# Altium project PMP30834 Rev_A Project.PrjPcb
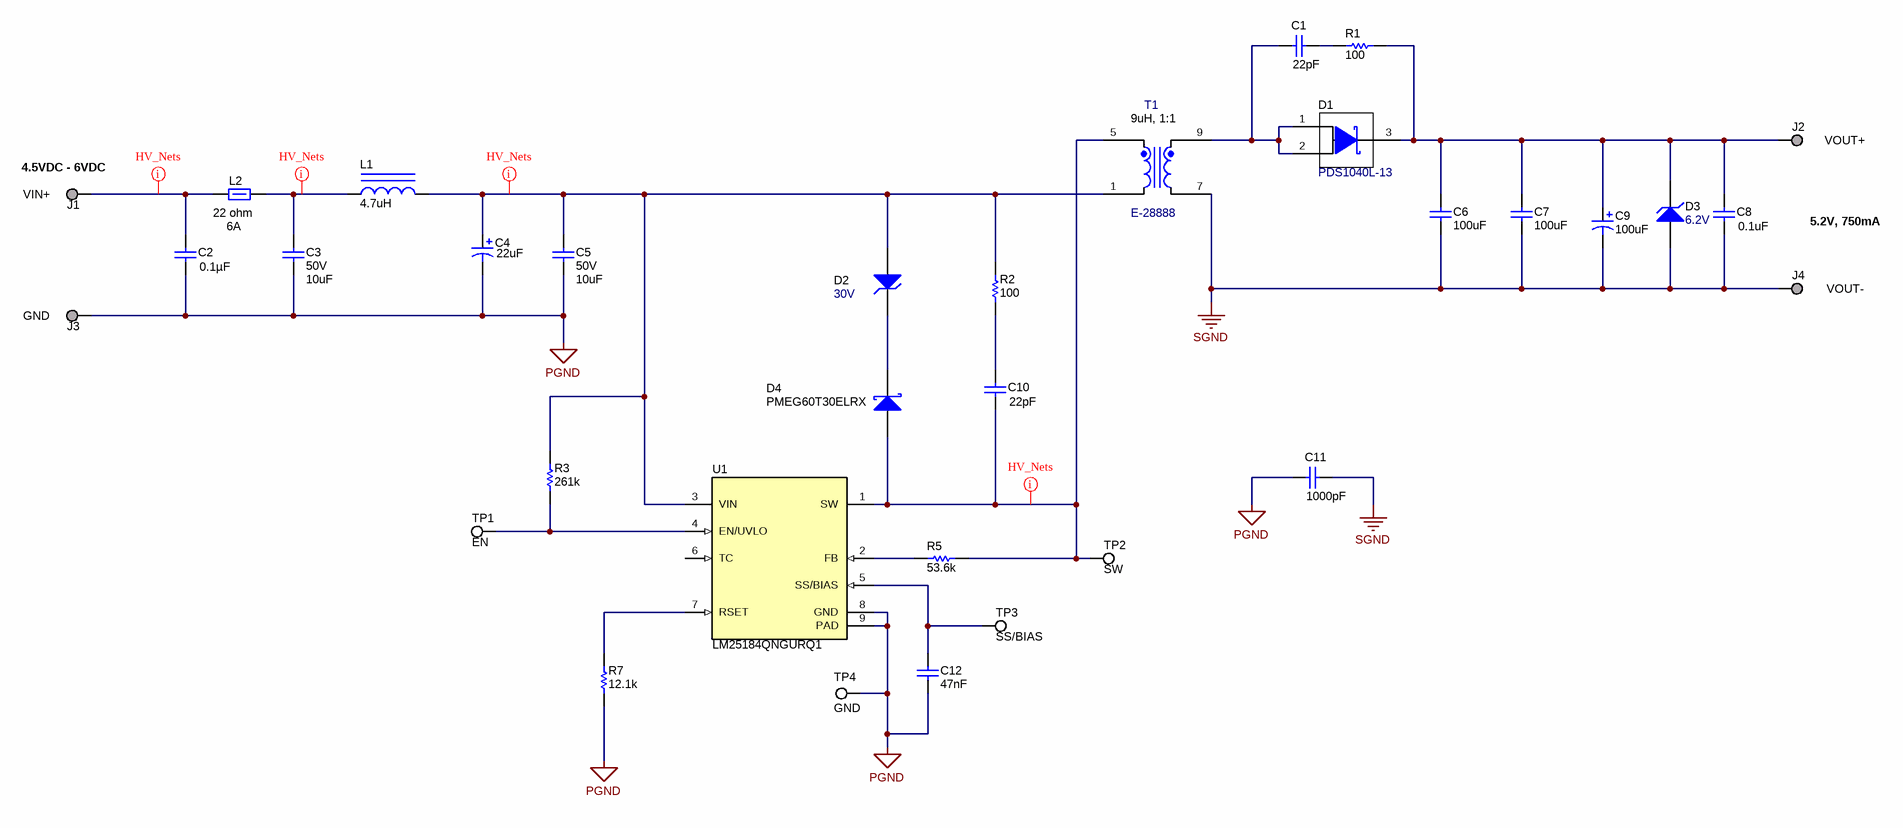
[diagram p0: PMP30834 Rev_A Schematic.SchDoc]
TID: N/A; TechSupport: http://www.ti.com/support; SCH_Rev: A; PRJ_Title: LM25184 Flyback Converter; PRJ_Number: PMP30834; PRJ_Engineer: R. Scibilia; PRJ_Customer: Public Release; PCB_Rev: A; PCB_Layout: K Nielson; CopyrightYear: 2020
2 sheets, 54 parts. Net scope: global (net labels, ports and power ports of the same name join across sheets).
Board file: PMP30834 Rev_A PCB.PcbDoc
Sheets:
  PMP30834 Rev_A Schematic.SchDoc
  PMP30834 Rev_A-HW.SchDoc

## Sheet PMP30834 Rev_A Schematic.SchDoc: LM25184 Flyback Converter - Schematic
size 431 x 279 mm; Date: Not shown in title block; ApprovedBy: Not shown in title block; CheckedBy: Not shown in title block; Author: Not shown in title block; CompanyName: Not shown in title block; DrawnBy: R. Scibilia; Engineer: Not shown in title block; Organization: Not shown in title block; Address1: Not shown in title block; Address2: Not shown in title block; Address3: Not shown in title block; Address4: Not shown in title block; DocumentNumber: 1; Revision: Use project parameter SCH_Rev; SheetNumber: 1; SheetTotal: 2; PageSetup: Record=PageOptions¦CenterHorizontal=True¦CenterVertical=True¦PrintScale=1.00¦XCorrection=1.00¦YCorrection=1.00¦PrintKind=0¦BorderSize=5000000¦LeftOffset=0¦BottomOffset=0¦Orientation=2¦PaperLength=1000¦PaperWidth=1000¦Scale=100¦PaperSource=15¦PrintQuality=600¦MediaType=1¦DitherType=10¦PaperKind=Letter¦PrintScaleMode=1

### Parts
C1  ValueDisplayed: 22pF  [0603_HV]  (hidden comment: GRM1885C2A220JA01D)
C2  ValueDisplayed: 0.1µF  [0603]  (hidden comment: C0603C104K5RACAUTO)
C3  VDC_V: 50V  ValueDisplayed: 10uF  [1210_280]  (hidden comment: CGA6P3X7S1H106K250AB)
C4  ValueDisplayed: 22uF  [Panasonic_D]  (hidden comment: EEH-ZC1H220P)
C5  VDC_V: 50V  ValueDisplayed: 10uF  [1210_280]  (hidden comment: CGA6P3X7S1H106K250AB)
C6  ValueDisplayed: 100uF  [1210_280]  (hidden comment: C1210C107M9PACTU)
C7  ValueDisplayed: 100uF  [1210_280]  (hidden comment: C1210C107M9PACTU)
C8  value 0.1uF  [0603L]  (hidden comment: C0603C104K5RACAUTO)
C9  ValueDisplayed: 100uF  [7343-31]  (hidden comment: T598D107M016ATE050)
C10  ValueDisplayed: 22pF  [0603_HV]  (hidden comment: GRM1885C2A220JA01D)
C11  ValueDisplayed: 1000pF  [1206_190]  (hidden comment: 202R18W102KV4E)
C12  Cap_F: 47nF  [0603L]  (hidden comment: GCM188R71E473KA37D)
D1  PDS1040L-13  [POWERDI5]
D2  value 30V  [SMA]  (hidden comment: 3SMAJ5936B-TP)
D3  value 6.2V  [SOD-523]  (hidden comment: BZT52C6V2T-7)
D4  PMEG60T30ELRX  [SOD-123W]
J1  1573-2  [Keystone1573-2]  (value not drawn)
J2  1573-2  [Keystone1573-2]  (value not drawn)
J3  1573-2  [Keystone1573-2]  (value not drawn)
J4  1573-2  [Keystone1573-2]  (value not drawn)
L1  ValueDisplayed: 4.7uH  [XFL4030]  (hidden comment: XFL4030-472MEB)
L2  value 22 ohm  Value2: 6A  [0805_HV]  (hidden comment: 742792021)
R1  ValueDisplayed: 100  [0603L]  (hidden comment: CRCW0603100RFKEA)
R2  ValueDisplayed: 100  [0603L]  (hidden comment: CRCW0603100RFKEA)
R3  ValueDisplayed: 261k  [0603_HV]  (hidden comment: CRCW0603261KFKEA)
R5  ValueDisplayed: 53.6k  [0603]  (hidden comment: RC0603FR-0753K6L)
R7  ValueDisplayed: 12.1k  [0603L]  (hidden comment: CRCW060312K1FKEA)
T1  E-28888  ValueDisplayed: 9uH, 1:1  [Coilcraft_PA6719-AE]
TP1  EN  [Testpoint_Keystone_Miniature]
TP2  SW  [Testpoint_Keystone_Miniature]
TP3  SS/BIAS  [Testpoint_Keystone_Miniature]
TP4  GND  [Testpoint_Keystone_Miniature]
U1  LM25184QNGURQ1  [NGU0008C]

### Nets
PGND: C2.2 C3.1 C4.2(-) C5.1 C11.2 C12.2 J3.1 R7.1 TP4.1 U1.8(GND) U1.9(PAD)
SGND: C6.1 C7.1 C8.2 C9.2(-) C11.1 D3.2(A) J4.1 T1.7
NetC1_1: C1.1 R1.2
NetC1_2: C1.2 D1.1(A) D1.2(A) T1.9
NetC2_1: C2.1 J1.1 L2.1
NetC3_2: C3.2 L1.1 L2.2
NetC4_1: C4.1(+) C5.2 D2.2(A) L1.2 R2.2 R3.2 T1.1 U1.3(VIN)
NetC6_2: C6.2 C7.2 C8.1 C9.1(+) D1.3(K) D3.1(K) J2.1 R1.1
NetC10_1: C10.1 R2.1
NetC10_2: C10.2 D4.2(A) R5.2 T1.5 TP2.1 U1.1(SW)
NetC12_1: C12.1 TP3.1 U1.5(SS/BIAS)
NetD2_1: D2.1(K) D4.1(K)
NetR3_1: R3.1 TP1.1 U1.4(EN/UVLO)
NetR5_1: R5.1 U1.2(FB)
NetR7_2: R7.2 U1.7(RSET)

Not connected (* = marked no-connect by the designer): U1 6(TC)

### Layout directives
net class HV_Nets: NetC2_1, NetC3_2, NetC4_1, NetC10_2

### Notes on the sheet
- (near J1) 4.5VDC - 6VDC
- (near J2) VOUT+
- (near J1) VIN+
- 5.2V, 750mA
- (near J3) GND
- (near J4) VOUT-

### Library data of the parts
C1 = CMP-0007255-4: CAP, CERM, 22 pF, 100 V, +/- 5%, C0G/NP0, 0603; Manufacturer: MuRata; TaMin_C: -55°C; Polarized: N; SizeAreaWB_mm2: 4.68; U/M: EA; Value: 22pF; TaMax_C: 125°C; SizeZ_mm: 1; SizeX_mm: 1.6; SizeY_mm: 0.8; Cap_Case: 0603; Value2: 100V; SizeArea_mm2: 1.28; CompType: Capacitor; AEC Category: Q200; Value1: Unknown
C2 = CMP-0079602-1: CAP, CERM, 0.1 µF, 50 V,+/- 10%, X7R, AEC-Q200 Grade 1, 0603; Manufacturer: Kemet; TaMin_C: -55°C; Polarized: N; SizeAreaWB_mm2: 4.68; U/M: EA; Value: 0.1uF; TaMax_C: 125°C; SizeZ_mm: 1; SizeX_mm: 1.6; SizeY_mm: 0.8; Value2: 50V; SizeArea_mm2: 1.28; AEC Qualified: Y; Cap_F: 100nF; AEC Category: Q200
C3 C5 = CMP-0009164-2: CAP, CERM, 10 uF, 50 V, +/- 10%, X7S, AEC-Q200 Grade 1, 1210; Manufacturer: TDK; TaMin_C: -55°C; Polarized: N; SizeAreaWB_mm2: 14.7; Value1: 0.002827 ohm; U/M: EA; Value: 10uF; TaMax_C: 125°C; SizeZ_mm: 2.8; SizeX_mm: 3.2; SizeY_mm: 2.5; SizeArea_mm2: 8; AEC Qualified: Y; Cap_F: 10µF; AEC Grade: 1; AEC Category: Q200; ESR_ohm: 2.827m; IRMS_A: 4.37286A
C4 = CMP-0012597-3: CAP, Polymer Hybrid, 22 uF, 50 V, +/- 20%, 0.08 ohm, AEC-Q200 Grade 1, D6.3xL5.8mm SMD; Manufacturer: Panasonic; TaMin_C: -55°C; ESR_ohm: 0.08; Polarized: Y; SizeAreaWB_mm2: 73.96; Value: 22uF; TaMax_C: 125°C; SizeZ_mm: 6.1; SizeX_mm: 6.6; Cap_Case: 6.3x5.8; Value2: 50V; SizeArea_mm2: 43.56; CompType: Capacitor; Cap_F: 22µF; IRMS_A: 750mA; AEC Grade: 1; AEC Category: Q200
C6 C7 = CMP-0009083-2: CAP, CERM, 100 uF, 6.3 V, +/- 20%, X5R, 1210; Manufacturer: Kemet; TaMin_C: -55°C; Polarized: N; SizeAreaWB_mm2: 14.7; Value1: Unknown; U/M: EA; Value: 100uF; TaMax_C: 85°C; SizeZ_mm: 2.8; SizeX_mm: 3.2; SizeY_mm: 2.5; Cap_Case: 1210; Value2: 6.3V; SizeArea_mm2: 8; Cap_F: 100µF; AEC Category: Q200
C8 = CMP-0079602-1: CAP, CERM, 0.1 µF, 50 V,+/- 10%, X7R, AEC-Q200 Grade 1, 0603; Manufacturer: Kemet; TaMin_C: -55°C; Polarized: N; SizeAreaWB_mm2: 4.68; U/M: EA; TaMax_C: 125°C; SizeZ_mm: 1; SizeX_mm: 1.6; SizeY_mm: 0.8; Cap_Case: 0603; Value2: 50V; SizeArea_mm2: 1.28; AEC Qualified: Y; Cap_F: 100nF; AEC Category: Q200; ValueDisplayed: 0.1µF
C9 = CMP-0012660-3: CAP, Tantalum Polymer, 100 uF, 16 V, +/- 20%, 0.05 ohm, AEC-Q200 Grade 1, 7343-31 SMD; Manufacturer: Kemet; TaMin_C: -55°C; ESR_ohm: 0.05; Polarized: Y; SizeAreaWB_mm2: 58.59; Value: 100uF; TaMax_C: 125°C; SizeZ_mm: 3.1; SizeX_mm: 7.3; SizeY_mm: 4.3; Value2: 16V; SizeArea_mm2: 31.39; CompType: Capacitor; Cap_F: 100µF; IRMS_A: 2.121A; AEC Grade: 1; AEC Category: Q200
C10 = CMP-0007255-4: CAP, CERM, 22 pF, 100 V, +/- 5%, C0G/NP0, 0603; Manufacturer: MuRata; TaMin_C: -55°C; Polarized: N; SizeAreaWB_mm2: 4.68; Value1: Unknown; U/M: EA; Value: 22pF; TaMax_C: 125°C; SizeZ_mm: 1; SizeX_mm: 1.6; SizeY_mm: 0.8; Cap_Case: 0603; Value2: 100V; SizeArea_mm2: 1.28; CompType: Capacitor; AEC Category: Q200
C11 = CMP-0008572-2: CAP, CERM, 1000 pF, 2000 V, +/- 10%, X7R, 1206_190; Manufacturer: Johanson Technology; TaMin_C: -55°C; Polarized: N; SizeAreaWB_mm2: 10.92; Value1: Unknown; U/M: EA; Value: 1000pF; TaMax_C: 125°C; SizeZ_mm: 1.9; SizeX_mm: 3.2; SizeY_mm: 1.6; Cap_Case: 1206; Value2: 2000V; SizeArea_mm2: 5.12; CompType: Capacitor; Cap_F: 1nF; VDC_V: 2kV; AEC Category: Q200
C12 = CMP-0007141-3: CAP, CERM, 0.047 uF, 25 V, +/- 10%, X7R, AEC-Q200 Grade 1, 0603; Manufacturer: MuRata; TaMin_C: -55°C; Polarized: N; SizeAreaWB_mm2: 4.68; Value1: Unknown; U/M: EA; TaMax_C: 125°C; SizeZ_mm: 1; SizeX_mm: 1.6; SizeY_mm: 0.8; Cap_Case: 0603; Value2: 25V; SizeArea_mm2: 1.28; AEC Qualified: Y; AEC Category: Q200
D1 = CMP-0028634-2: Diode, Schottky, 40 V, 10 A, PowerDI5; Manufacturer: Diodes Inc.; Value2: 0.49V; Vf_V: 490mV; AEC Category: Q101; Value1: 10A; RJC_CperW: 85; Green_Lifecycle: Active; SizeY_mm: 3.9; SizeArea_mm2: 24.96; Vr_V: 40V; Green_REACh: Passed; SizeX_mm: 6.4; TJmax_C: 150°C; SizeZ_mm: 1.05; SizeAreaWB_mm2: 49.56
D2 = CMP-0005515-3: Diode, Zener, 30 V, 3 W, SMA; Manufacturer: Micro Commercial Components; SizeArea_mm2: 16.3228; Value1: 3W; SizeY_mm: 2.92; SizeX_mm: 5.59; RJA_CperW: 226; SizeZ_mm: 2.87; SizeAreaWB_mm2: 37.3428; AEC Category: Q101
D3 = CMP-0005901-1: Diode, Zener, 6.2 V, 300 mW, SOD-523; Manufacturer: Diodes Inc.; Power_W: 300mW; SizeAreaWB_mm2: 5.13; Value1: 0.3W; RJA_CperW: 417; U/M: EA; SizeZ_mm: 0.65; SizeX_mm: 1.7; SizeY_mm: 0.9; SizeArea_mm2: 1.53; AEC Category: Q101
D4 = CMP-0085903-1: Diode, Schottky, 60 V, 3 A, AEC-Q101, SOD-123W; Manufacturer: Nexperia; Io_A: 3A; SizeAreaWB_mm2: 12.15; Vr_V: 60V; TJmax_C: 175°C; SizeZ_mm: 1; SizeX_mm: 3.5; SizeY_mm: 1.7; Vf_V: 620mV; Value2: 0.62V; SizeArea_mm2: 5.95; AEC Qualified: Y; AEC Category: Q101
J1-J4 = CMP-0055119-1: Terminal, Turret, TH, Double; Manufacturer: Keystone; CT: FALSE; Green_REACh: Passed; CompType: Turret Terminal; Green_Lifecycle: Active
L1 = CMP-0061153-1: Inductor, Shielded, Composite, 4.7 uH, 2.1 A, 0.03 ohm, SMD; Manufacturer: Coilcraft; Isat: 2.1A @ 30% inductance drop; Irms: 7.5A @ 40C rise; Green_Lifecycle: Not Set; SizeAreaWB_mm2: 25; DCR_ohm: 0.03; Green_REACh: Incomplete; Value: 4.7uH; Imax_A: 2.1A; SizeZ_mm: 3.1; SizeX_mm: 4; SizeArea_mm2: 16; Ind_H: 4.7µH; AEC Qualified: N; AEC Category: Q200
L2 = CMP-0003072-1: Ferrite Bead, 22 ohm @ 100 MHz, 6 A, 0805; Manufacturer: Wurth Elektronik; Ztyp@1GHz_Ohm: 40.219; ZTyp@100MHz_Ohm: 22; SizeAreaWB_mm2: 6.75; DCR_ohm: 8m; Value1: 0.008 ohm; SizeZ_mm: 1.45; SizeX_mm: 2; SizeY_mm: 1.25; SizeArea_mm2: 2.5
R1 R2 = CMP-0021991-4: RES, 100, 1%, 0.1 W, AEC-Q200 Grade 0, 0603; Manufacturer: Vishay-Dale; Power_W: 100mW; TempCo: 100 ppm/C; Value_Code: 100R; Value: 100; EIA_Code: E96; SizeX_mm: 1.6; SizeY_mm: 0.8; SizeZ_mm: 1; Value2: 0.1W; SizeArea_mm2: 1.28; AEC Qualified: Y; VDC_V: 75V; AEC Category: Q200; AEC Grade: 0
R3 = CMP-0022244-4: RES, 261 k, 1%, 0.1 W, AEC-Q200 Grade 0, 0603; Manufacturer: Vishay-Dale; Power_W: 100mW; TempCo: 100 ppm/C; Value: 261k; EIA_Code: E96; SizeX_mm: 1.6; SizeY_mm: 0.8; SizeZ_mm: 1; Value2: 0.1W; SizeArea_mm2: 1.28; AEC Qualified: Y; VDC_V: 75V; AEC Category: Q200; AEC Grade: 0
R5 = CMP-0023176-5: RES, 53.6 k, 1%, 0.1 W, 0603; Manufacturer: Yageo; Power_W: 100mW; TempCo: 100 ppm/C; Value_Code: 53k6; Value: 53.6k; EIA_Code: E96; SizeX_mm: 1.6; SizeY_mm: 0.8; SizeZ_mm: 1; Value2: 0.1W; SizeArea_mm2: 1.28; AEC Qualified: N; VDC_V: 75V; AEC Category: Q200; SizeAreaWB_mm2: 4.68
R7 = CMP-0022030-4: RES, 12.1 k, 1%, 0.1 W, AEC-Q200 Grade 0, 0603; Manufacturer: Vishay-Dale; Power_W: 100mW; TempCo: 100 ppm/C; Value_Code: 12k1; Value: 12.1k; EIA_Code: E96; SizeX_mm: 1.6; SizeY_mm: 0.8; SizeZ_mm: 1; Value2: 0.1W; SizeArea_mm2: 1.28; AEC Qualified: Y; VDC_V: 75V; AEC Category: Q200; AEC Grade: 0
T1 = CMP-0030170-2: Transformer, Flyback, SMT; Manufacturer: Custom; LeakageInd_H: 500nH; Ind_H: 9µH; Lp: 9; DCR_ohm: 45m
TP1-TP4 = CMP-0055152-1: Test Point, Miniature, SMT; Manufacturer: Keystone; PartNumber: 5015; CNHeader: FALSE; Green_Lifecycle: Active; Green_REACh: Passed; CT: TRUE
U1 = CMP-0860959-2: 42-VIN PSR Flyback DC/DC Converter with 65-V, 4-A Integrated MOSFET, NGU0008C (WSON-8); Manufacturer: Texas Instruments; SizeArea_mm2: 16; SizeY_mm: 4; SizeAreaWB_mm2: 25; CompType: IC; AEC Category: Q200; SizeZ_mm: 0.8; AEC Qualified: Y

## Sheet PMP30834 Rev_A-HW.SchDoc: LM25184 Flyback Converter - Hardware
size 431 x 279 mm; Date: Not shown in title block; ApprovedBy: Not shown in title block; CheckedBy: Not shown in title block; Author: Not shown in title block; CompanyName: Not shown in title block; DrawnBy: R. Scibilia; Engineer: Not shown in title block; Organization: Not shown in title block; Address1: Not shown in title block; Address2: Not shown in title block; Address3: Not shown in title block; Address4: Not shown in title block; DocumentNumber: 2; Revision: Use project parameter SCH_Rev; SheetNumber: 2; SheetTotal: 2; PageSetup: Record=PageOptions¦CenterHorizontal=True¦CenterVertical=True¦PrintScale=1.00¦XCorrection=1.00¦YCorrection=1.00¦PrintKind=0¦BorderSize=5000000¦LeftOffset=0¦BottomOffset=0¦Orientation=2¦PaperLength=1000¦PaperWidth=1000¦Scale=100¦PaperSource=15¦PrintQuality=600¦MediaType=1¦DitherType=10¦PaperKind=Letter¦PrintScaleMode=1
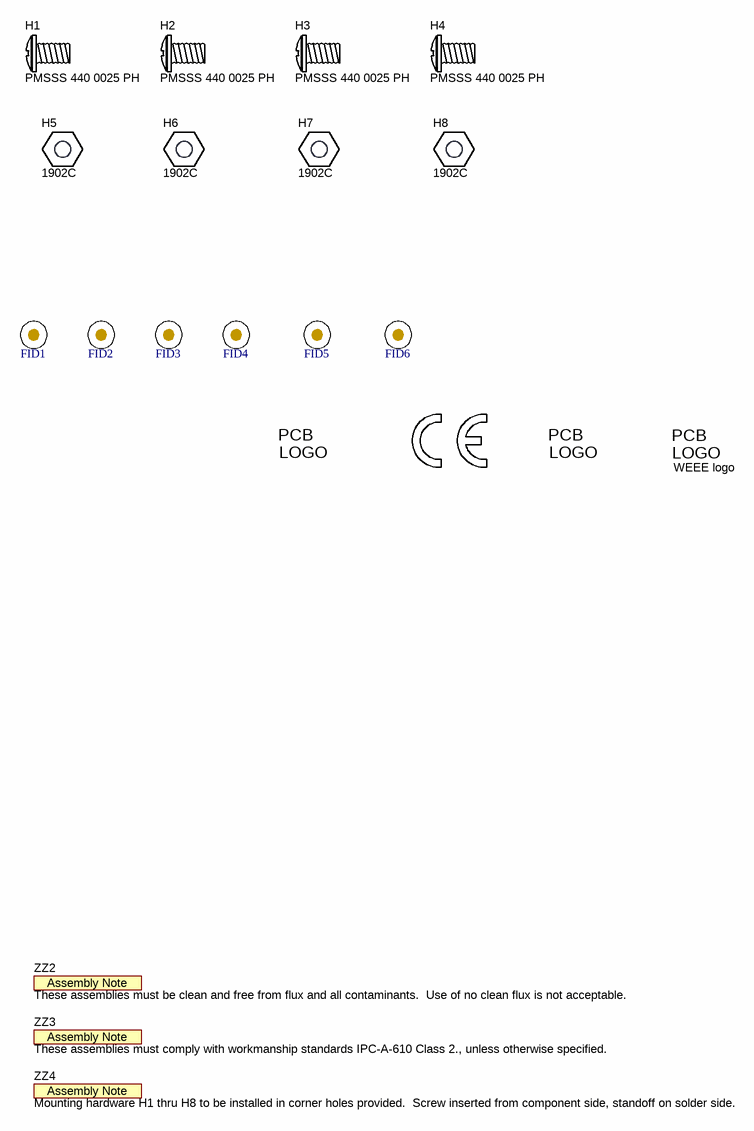
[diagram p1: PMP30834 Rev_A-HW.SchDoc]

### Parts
FID1  Fiducial  [Fiducial10-20]  (value not drawn)
FID2  Fiducial  [Fiducial10-20]  (value not drawn)
FID3  Fiducial  [Fiducial10-20]  (value not drawn)
FID4  Fiducial  [Fiducial10-20]  (value not drawn)
FID5  Fiducial  [Fiducial10-20]  (value not drawn)
FID6  Fiducial  [Fiducial10-20]  (value not drawn)
H1  PMSSS 440 0025 PH  [B_F_PMSSS4400025PH]
H2  PMSSS 440 0025 PH  [B_F_PMSSS4400025PH]
H3  PMSSS 440 0025 PH  [B_F_PMSSS4400025PH]
H4  PMSSS 440 0025 PH  [B_F_PMSSS4400025PH]
H5  1902C  [Keystone_1902C]
H6  1902C  [Keystone_1902C]
H7  1902C  [Keystone_1902C]
H8  1902C  [Keystone_1902C]
Logo1  Texas Instruments  [TI_Stacked_Overlay_Small]  (value not drawn)  (no BOM)
Logo2  WEEE logo  [WEEE_Minimum]  (no BOM)
Logo3  FCC disclaimer  [FCC_disclaimer_stacked]  (value not drawn)  (no BOM)
LOGO4  CE Mark  [CE_Mark_5mm]  (value not drawn)  (no BOM)
ZZ2  These assemblies must be clean and free from flux and all contaminants.  Use of no clean flux is not acceptable.  [AssemblyNote]  (no BOM)
ZZ3  These assemblies must comply with workmanship standards IPC-A-610 Class 2., unless otherwise specified.  [AssemblyNote]  (no BOM)
ZZ4  Mounting hardware H1 thru H8 to be installed in corner holes provided.  Screw inserted from component side, standoff on solder side.  [AssemblyNote]  (no BOM)

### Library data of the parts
FID1-FID6 = CMP-0077181-1: Fiducial mark.  There is nothing to buy or mount.
H1 H2 H4 = CMP-0003715-1: MACHINE SCREW PAN PHILLIPS 4-40; Manufacturer: B&F Fastener Supply; CompType: Standoff; Component Classes: MountingHoles
H3 = CMP-0003715-1: MACHINE SCREW PAN PHILLIPS 4-40; Manufacturer: B&F Fastener Supply; CompType: Standoff; Component Classes: MountingHoles; Rule: PcbType=ProtelPcb
H5-H8 = CMP-0003610-1: Standoff, Hex, 0.5"L #4-40 Nylon; Manufacturer: Keystone; CompType: Hardware; Component Classes: MountingHoles
Logo1 = CMP-0074838-1: Texas Instrument Corporate Signature; SymbolCreator: a0412235; Lib Reference: TI_Logo
Logo2 = CMP-0074769-1
Logo3 = CMP-0074847-1: FCC_disclaimer
LOGO4 = CMP-0074844-1: SymbolCreator: a0412235
ZZ2-ZZ4 = AssemblyNote: SymbolCreator: codlsc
